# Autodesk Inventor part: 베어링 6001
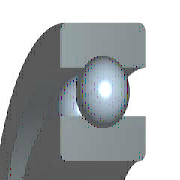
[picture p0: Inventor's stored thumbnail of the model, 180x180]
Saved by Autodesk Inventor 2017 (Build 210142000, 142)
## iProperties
Created: 2012-02
Part Number: 베어링 6001
Material: 강철, 연강
Description: 깊은 그루브 볼 베어링
Document SubType Name: Modeling
Standard: KS B 2023
Designer: mduedu
Standards Organization: KS
Language: ko-KR
Size Designation: 6001 - 12 x 28 x 8
Categories: <MemberInstance><Categories><Category DisplayName="샤프트 부품" InternalName="7f7aeb1f-a693-4053-b835-cee3144e0d98" Mnemonic="SHFT"><Category DisplayName="베어링" Inter
Density: 7.86 g/cm^3
Mass: 21.4855 g
Surface Area: 31.1809 cm^2
Volume: 2.73352 cm^3
Appearance: 노란색
IsCustomPart: 1
Author: mduedu
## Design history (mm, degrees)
sketch "스케치" dims "d0" = 4.16 (= -0.26 x WD + 0.26 x BD)
  geometry: L1 (1.92, 10)-(6.08, 10); L2 (4, 10)-(4, 7.92); L3 (4, 10)-(4, 12.08); L4 (2.454, 8.608)-(0, 8.608); L5 (0, 6)-(8, 6); L6 (2.454, 11.392)-(0, 11.392); L7 (0, 14)-(8, 14); L8 (8, 6)-(8, 8.608); L9 (5.546, 8.608)-(8, 8.608); L10 (5.546, 11.392)-(8, 11.392); L11 (8, 14)-(8, 11.392); L12 (-1.4, 0)-(8.4, 0) reference; L13 (0, -0.3)-(0, 5.3) reference
  constraints: 22 end point, 4 point on line, 2 collinear, 2 perpendicular, 2 symmetric about line, 1 midpoint, 1 parallel, 14 other
  dimensions: "d9" = 12 diameter of L5 L12 (= WD); "d11" = 28 diameter of L7 L12 (= BD); "d12" = 8 distance between parallel lines of L8 L13 (= KB); "d13" = 17.216 diameter of L9 L12 (= 0.326 x BD + 0.674 x WD)
revolve "본체" stored, may be unused: angle "d6" = 90 deg
revolve "볼" stored, may be unused: angle "d7" = 90 deg
pattern_circular "IDS_ARRAYBALL[SIMPL:T]" dims angle "d3" = 360 deg
body "Solid1"
fillet "모깎기1" dims "d1" = 0.3 (= KRS)
other parameters: "WD" = 12 [user parameter; used in 5 equation terms], "BD" = 28 [user parameter; used in 5 equation terms], "KB" = 8 [user parameter; used in 1 equation term], "KRS" = 0.3 [user parameter; used in 1 equation term], "d4" = 0, "d5" = 0, "d8" = 0, "d14" = 0, "d15" = 0, "BBA" = 0 [user parameter], "BC0" = 2360000 [user parameter], "BC" = 5070000 [user parameter], "BR" = 14 (= 0.5 x BD) [user parameter], "WR" = 6 (= 0.5 x WD) [user parameter]
